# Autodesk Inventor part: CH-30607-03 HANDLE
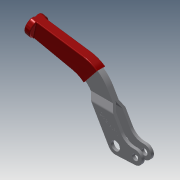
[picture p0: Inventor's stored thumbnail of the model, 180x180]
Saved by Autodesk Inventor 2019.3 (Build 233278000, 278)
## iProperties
Created: 2012-09
Part Number: CH-30607-03 HANDLE
Material: Ogólny
Document SubType Name: Modeling
Designer: CADENGINEERING4
Density: 1 g/cm^3
Appearance: Domyślna
Author: CADENGINEERING4
Revision Number: ÈÎºÎ
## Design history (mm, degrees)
feature "NONE"
node "Bryła1"
